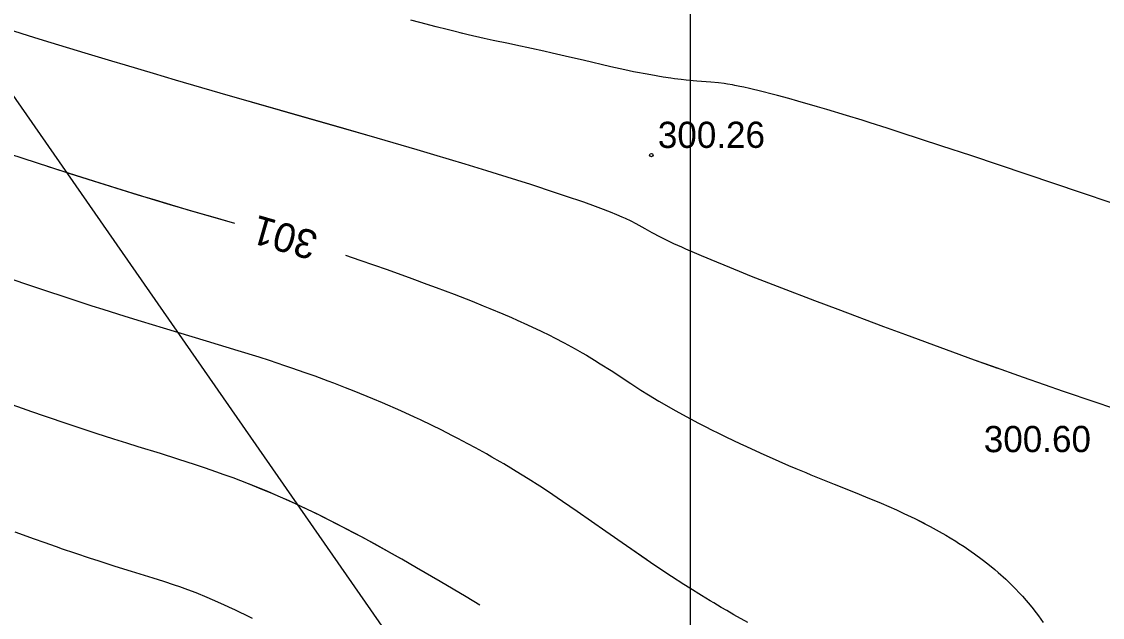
# Model space of a CAD drawing. Extents: x 7477803 to 7478145, y 5500698 to 5500984.
# Drawn here: x 7477982.63 to 7478010.69, y 5500826.14 to 5500841.6 of the extents above; entities that cross this region are included whole.
import ezdxf

# ---------------------------------------------------------------- set-up
doc = ezdxf.new("R2010")
doc.units = 0
for name, color, linetype in [('gr_klasy', 7, 'Continuous'), ('pkt_wys', 7, 'Continuous'), ('robocza49', 7, 'Continuous'), ('warst_ciagla', 7, 'Continuous'), ('warst_opis', 7, 'Continuous'), ('warst_pogrub', 7, 'Continuous'), ('warst_przeryw', 7, 'Continuous')]:
    doc.layers.add(name, color=color, linetype=linetype)

# ---------------------------------------------------------------- blocks, each defined once
blk = doc.blocks.new('801_1')
at = {"layer": 'pkt_wys'}
blk.add_circle((0, 0), 0.045, dxfattribs=at)
blk.add_circle((0, 0), 0.045, dxfattribs=at)

msp = doc.modelspace()

# ---------------------------------------------------------------- linework, layer by layer
at = {"layer": 'gr_klasy'}
msp.add_lwpolyline([(7477998.08, 5500817.16), (7477980.49, 5500842.45)], dxfattribs=at)
at = {"layer": 'robocza49'}
msp.add_line((7478000, 5500750), (7478000, 5500973.047), dxfattribs=at)
at = {"layer": 'warst_ciagla'}
for points in [[(7477982.322, 5500838.165), (7477983.358, 5500837.827), (7477983.907, 5500837.651), (7477984.763, 5500837.382), (7477985.648, 5500837.108), (7477986.098, 5500836.972), (7477987.01, 5500836.7), (7477987.468, 5500836.566), (7477988.155, 5500836.369)], [(7477983.299, 5500837.846), (7477984.198, 5500837.559), (7477984.664, 5500837.413), (7477985.38, 5500837.191), (7477986.111, 5500836.968), (7477986.48, 5500836.857), (7477987.223, 5500836.637), (7477987.596, 5500836.529), (7477988.155, 5500836.369)], [(7477991.039, 5500835.541), (7477991.416, 5500835.41), (7477992.12, 5500835.163), (7477992.758, 5500834.933), (7477993.15, 5500834.79), (7477993.396, 5500834.698), (7477993.857, 5500834.524), (7477994.325, 5500834.342), (7477994.611, 5500834.228), (7477994.79, 5500834.155), (7477995.123, 5500834.017), (7477995.353, 5500833.918), (7477995.496, 5500833.855), (7477995.764, 5500833.735), (7477996.122, 5500833.566), (7477996.336, 5500833.461), (7477996.469, 5500833.394), (7477996.716, 5500833.264), (7477997.003, 5500833.107), (7477997.18, 5500833.006), (7477997.292, 5500832.941), (7477997.504, 5500832.814), (7477997.653, 5500832.722), (7477997.934, 5500832.544), (7477998.451, 5500832.206), (7477998.706, 5500832.041), (7477998.904, 5500831.918), (7477999.175, 5500831.755), (7477999.315, 5500831.673), (7477999.601, 5500831.509), (7477999.999, 5500831.292), (7478000.205, 5500831.183), (7478000.362, 5500831.101), (7478000.576, 5500830.993), (7478000.685, 5500830.938), (7478000.933, 5500830.816), (7478001.273, 5500830.654), (7478001.446, 5500830.573), (7478001.801, 5500830.41), (7478002.29, 5500830.194), (7478002.542, 5500830.086), (7478002.733, 5500830.005), (7478002.992, 5500829.898), (7478003.123, 5500829.844), (7478003.726, 5500829.601), (7478004.269, 5500829.383), (7478004.541, 5500829.272), (7478004.946, 5500829.103), (7478005.343, 5500828.929), (7478005.537, 5500828.841), (7478005.823, 5500828.704), (7478006.078, 5500828.576)], [(7477991.039, 5500835.541), (7477991.416, 5500835.41), (7477992.12, 5500835.163), (7477992.758, 5500834.933), (7477993.15, 5500834.79), (7477993.396, 5500834.698), (7477993.857, 5500834.524), (7477994.325, 5500834.342), (7477994.611, 5500834.228), (7477994.79, 5500834.155), (7477995.123, 5500834.017), (7477995.353, 5500833.918), (7477995.496, 5500833.855), (7477995.764, 5500833.735), (7477996.122, 5500833.566), (7477996.336, 5500833.461), (7477996.469, 5500833.394), (7477996.716, 5500833.264), (7477997.003, 5500833.107), (7477997.18, 5500833.006), (7477997.292, 5500832.941), (7477997.504, 5500832.814), (7477997.653, 5500832.722), (7477997.934, 5500832.544), (7477998.451, 5500832.206), (7477998.706, 5500832.041), (7477998.904, 5500831.918), (7477999.175, 5500831.755), (7477999.315, 5500831.673), (7477999.601, 5500831.509), (7477999.999, 5500831.292), (7478000.205, 5500831.183), (7478000.362, 5500831.101), (7478000.576, 5500830.993), (7478000.685, 5500830.938), (7478000.933, 5500830.816), (7478001.273, 5500830.654), (7478001.446, 5500830.573), (7478001.801, 5500830.41), (7478002.29, 5500830.194), (7478002.542, 5500830.086), (7478002.733, 5500830.005), (7478002.992, 5500829.898), (7478003.123, 5500829.844), (7478003.726, 5500829.601), (7478004.269, 5500829.383), (7478004.541, 5500829.272), (7478004.946, 5500829.103), (7478005.343, 5500828.929), (7478005.537, 5500828.841), (7478005.823, 5500828.704), (7478006.099, 5500828.565), (7478006.219, 5500828.501), (7478006.377, 5500828.415), (7478006.454, 5500828.372), (7478006.625, 5500828.273), (7478006.737, 5500828.207), (7478006.883, 5500828.116), (7478006.955, 5500828.071), (7478007.097, 5500827.978), (7478007.281, 5500827.853), (7478007.371, 5500827.79), (7478007.567, 5500827.645), (7478007.71, 5500827.534), (7478007.895, 5500827.384), (7478007.984, 5500827.308), (7478008.178, 5500827.133), (7478008.262, 5500827.054), (7478008.371, 5500826.948), (7478008.424, 5500826.895), (7478008.54, 5500826.773), (7478008.616, 5500826.691), (7478008.713, 5500826.58), (7478008.761, 5500826.524), (7478008.854, 5500826.412), (7478008.973, 5500826.259), (7478009.03, 5500826.182), (7478009.154, 5500826.006)], [(7477994.526, 5500826.461), (7477994.17, 5500826.675), (7477993.501, 5500827.073), (7477992.883, 5500827.432), (7477992.499, 5500827.652), (7477992.254, 5500827.79), (7477991.791, 5500828.047), (7477991.308, 5500828.308), (7477991.008, 5500828.466), (7477990.817, 5500828.565), (7477990.454, 5500828.748), (7477990.198, 5500828.873), (7477990.034, 5500828.952), (7477989.723, 5500829.097), (7477989.575, 5500829.165), (7477989.29, 5500829.29), (7477989.021, 5500829.404), (7477988.849, 5500829.475), (7477988.519, 5500829.607), (7477988.121, 5500829.759), (7477987.866, 5500829.853), (7477987.701, 5500829.912), (7477987.378, 5500830.024), (7477987.143, 5500830.103), (7477986.686, 5500830.251), (7477986.242, 5500830.39), (7477985.655, 5500830.57), (7477985.36, 5500830.662), (7477985.024, 5500830.768), (7477984.567, 5500830.914), (7477984.335, 5500830.99), (7477983.864, 5500831.146), (7477983.223, 5500831.365), (7477982.895, 5500831.478), (7477982.144, 5500831.744)], [(7477992.472, 5500827.667), (7477991.863, 5500828.008), (7477991.487, 5500828.212), (7477991.25, 5500828.339), (7477990.803, 5500828.571), (7477990.492, 5500828.729), (7477990.294, 5500828.827), (7477989.921, 5500829.005), (7477989.745, 5500829.087), (7477989.41, 5500829.238), (7477989.097, 5500829.373), (7477988.898, 5500829.455), (7477988.519, 5500829.607), (7477988.121, 5500829.759), (7477987.866, 5500829.853), (7477987.701, 5500829.912), (7477987.378, 5500830.024), (7477987.143, 5500830.103), (7477986.686, 5500830.251), (7477986.242, 5500830.39), (7477985.655, 5500830.57), (7477985.36, 5500830.662), (7477985.024, 5500830.768), (7477984.567, 5500830.914), (7477984.335, 5500830.99), (7477983.864, 5500831.146), (7477983.223, 5500831.365), (7477982.895, 5500831.478), (7477982.144, 5500831.744)]]:
    msp.add_lwpolyline(points, dxfattribs=at)
at = {"layer": 'warst_pogrub'}
for points in [[(7478010.123, 5500837.166), (7478008.739, 5500837.631), (7478007.273, 5500838.121), (7478006.524, 5500838.369), (7478005.44, 5500838.723), (7478005.098, 5500838.833), (7478004.66, 5500838.972), (7478004.449, 5500839.038), (7478004.043, 5500839.164), (7478003.534, 5500839.318), (7478003.293, 5500839.39), (7478002.786, 5500839.536), (7478002.55, 5500839.602), (7478002.253, 5500839.682), (7478002.113, 5500839.719), (7478001.848, 5500839.786), (7478001.527, 5500839.863), (7478001.38, 5500839.895), (7478001.276, 5500839.917), (7478001.146, 5500839.942), (7478001.084, 5500839.953), (7478000.954, 5500839.975), (7478000.873, 5500839.988), (7478000.722, 5500840.008), (7478000.52, 5500840.028), (7478000.156, 5500840.055), (7477999.879, 5500840.081), (7477999.751, 5500840.095), (7477999.577, 5500840.117), (7477999.488, 5500840.129), (7477999.284, 5500840.16), (7477998.966, 5500840.213), (7477998.82, 5500840.24), (7477998.621, 5500840.278), (7477998.52, 5500840.298), (7477998.288, 5500840.347), (7477997.93, 5500840.427), (7477997.207, 5500840.597), (7477996.856, 5500840.679), (7477996.405, 5500840.781), (7477996.187, 5500840.83), (7477995.87, 5500840.899), (7477995.464, 5500840.986), (7477995.268, 5500841.026), (7477994.872, 5500841.108), (7477994.644, 5500841.157), (7477994.226, 5500841.254), (7477993.679, 5500841.39), (7477993.392, 5500841.464), (7477992.967, 5500841.575), (7477992.736, 5500841.636)], [(7478011.612, 5500836.666), (7478008.739, 5500837.631), (7478007.273, 5500838.121), (7478006.524, 5500838.369), (7478005.44, 5500838.723), (7478005.098, 5500838.833), (7478004.66, 5500838.972), (7478004.449, 5500839.038), (7478004.043, 5500839.164), (7478003.534, 5500839.318), (7478003.293, 5500839.39), (7478002.786, 5500839.536), (7478002.55, 5500839.602), (7478002.253, 5500839.682), (7478002.113, 5500839.719), (7478001.848, 5500839.786), (7478001.527, 5500839.863), (7478001.38, 5500839.895), (7478001.276, 5500839.917), (7478001.146, 5500839.942), (7478001.084, 5500839.953), (7478000.954, 5500839.975), (7478000.873, 5500839.988), (7478000.722, 5500840.008), (7478000.52, 5500840.028), (7478000.156, 5500840.055), (7477999.879, 5500840.081), (7477999.751, 5500840.095), (7477999.577, 5500840.117), (7477999.488, 5500840.129), (7477999.284, 5500840.16), (7477998.966, 5500840.213), (7477998.82, 5500840.24), (7477998.621, 5500840.278), (7477998.52, 5500840.298), (7477998.288, 5500840.347), (7477997.93, 5500840.427), (7477997.207, 5500840.597), (7477996.856, 5500840.679), (7477996.405, 5500840.781), (7477996.187, 5500840.83), (7477995.87, 5500840.899), (7477995.464, 5500840.986), (7477995.268, 5500841.026), (7477994.872, 5500841.108), (7477994.644, 5500841.157), (7477994.226, 5500841.254), (7477994.004, 5500841.309)]]:
    msp.add_lwpolyline(points, dxfattribs=at)
at = {"layer": 'warst_przeryw'}
for points in [[(7478007.973, 5500832.599), (7478007.364, 5500832.818), (7478006.641, 5500833.082), (7478005.585, 5500833.47), (7478005.018, 5500833.68), (7478003.825, 5500834.126), (7478003.226, 5500834.352), (7478002.364, 5500834.681), (7478001.583, 5500834.987), (7478001.264, 5500835.115), (7478000.866, 5500835.276), (7478000.678, 5500835.354), (7478000.285, 5500835.519), (7478000.103, 5500835.598), (7477999.875, 5500835.697), (7477999.768, 5500835.745), (7477999.566, 5500835.837), (7477999.325, 5500835.952), (7477999.216, 5500836.006), (7477998.999, 5500836.118), (7477998.816, 5500836.22), (7477998.585, 5500836.35), (7477998.457, 5500836.418), (7477998.309, 5500836.489), (7477998.225, 5500836.528), (7477998.084, 5500836.589), (7477997.921, 5500836.655), (7477997.671, 5500836.751), (7477997.532, 5500836.802), (7477997.224, 5500836.912), (7477996.755, 5500837.073), (7477996.495, 5500837.16), (7477995.847, 5500837.369), (7477995.49, 5500837.482), (7477994.982, 5500837.64), (7477994.713, 5500837.723), (7477994.147, 5500837.895), (7477993.333, 5500838.139), (7477992.901, 5500838.267), (7477991.865, 5500838.57), (7477990.168, 5500839.06), (7477987.79, 5500839.743), (7477986.624, 5500840.082), (7477986.06, 5500840.247), (7477985.33, 5500840.464), (7477984.975, 5500840.57), (7477984.284, 5500840.778), (7477983.402, 5500841.048), (7477982.978, 5500841.179), (7477982.067, 5500841.466)], [(7478011.415, 5500831.417), (7478010.501, 5500831.723), (7478009.674, 5500832.002), (7478009.184, 5500832.171), (7478008.636, 5500832.363), (7478007.814, 5500832.656), (7478007.364, 5500832.818), (7478006.641, 5500833.082), (7478005.585, 5500833.47), (7478005.018, 5500833.68), (7478003.825, 5500834.126), (7478003.226, 5500834.352), (7478002.364, 5500834.681), (7478001.583, 5500834.987), (7478001.264, 5500835.115), (7478000.866, 5500835.276), (7478000.678, 5500835.354), (7478000.285, 5500835.519), (7478000.103, 5500835.598), (7477999.875, 5500835.697), (7477999.768, 5500835.745), (7477999.566, 5500835.837), (7477999.325, 5500835.952), (7477999.216, 5500836.006), (7477998.999, 5500836.118), (7477998.816, 5500836.22), (7477998.585, 5500836.35), (7477998.457, 5500836.418), (7477998.309, 5500836.489), (7477998.225, 5500836.528), (7477998.084, 5500836.589), (7477997.921, 5500836.655), (7477997.671, 5500836.751), (7477997.532, 5500836.802), (7477997.224, 5500836.912), (7477996.755, 5500837.073), (7477996.495, 5500837.16), (7477995.847, 5500837.369), (7477995.49, 5500837.482), (7477994.982, 5500837.64), (7477994.713, 5500837.723), (7477994.147, 5500837.895), (7477993.333, 5500838.139), (7477992.901, 5500838.267), (7477991.865, 5500838.57), (7477990.791, 5500838.881), (7477988.517, 5500839.534)], [(7477998.86, 5500827.632), (7477998.331, 5500827.996), (7477997.798, 5500828.37), (7477997.058, 5500828.89), (7477996.675, 5500829.153), (7477996.284, 5500829.416), (7477996.085, 5500829.547), (7477995.782, 5500829.74), (7477995.474, 5500829.931), (7477995.336, 5500830.015), (7477995.15, 5500830.125), (7477995.056, 5500830.18), (7477994.843, 5500830.302), (7477994.7, 5500830.383), (7477994.508, 5500830.49), (7477994.411, 5500830.543), (7477994.217, 5500830.648), (7477993.954, 5500830.786), (7477993.822, 5500830.854), (7477993.521, 5500831.006), (7477993.293, 5500831.118), (7477992.985, 5500831.265), (7477992.829, 5500831.338), (7477992.476, 5500831.499), (7477991.997, 5500831.709), (7477991.754, 5500831.812), (7477991.262, 5500832.013), (7477991.04, 5500832.1), (7477990.741, 5500832.215), (7477990.591, 5500832.272), (7477990.25, 5500832.397), (7477989.991, 5500832.49), (7477989.643, 5500832.611), (7477989.467, 5500832.671), (7477989.068, 5500832.803), (7477988.8, 5500832.889), (7477988.257, 5500833.059), (7477987.431, 5500833.31), (7477986.312, 5500833.645), (7477985.747, 5500833.816), (7477985.322, 5500833.947), (7477984.753, 5500834.126), (7477984.467, 5500834.217), (7477983.895, 5500834.402), (7477983.129, 5500834.655), (7477982.744, 5500834.785), (7477981.875, 5500835.084)], [(7478001.487, 5500826.012), (7478001.124, 5500826.212), (7478000.938, 5500826.319), (7478000.796, 5500826.402), (7478000.603, 5500826.516), (7478000.505, 5500826.575), (7478000.282, 5500826.711), (7477999.977, 5500826.901), (7477999.821, 5500826.999), (7477999.505, 5500827.204), (7477999.069, 5500827.491), (7477998.846, 5500827.642), (7477998.331, 5500827.996), (7477997.798, 5500828.37), (7477997.058, 5500828.89), (7477996.675, 5500829.153), (7477996.284, 5500829.416), (7477996.085, 5500829.547), (7477995.782, 5500829.74), (7477995.474, 5500829.931), (7477995.336, 5500830.015), (7477995.15, 5500830.125), (7477995.056, 5500830.18), (7477994.843, 5500830.302), (7477994.7, 5500830.383), (7477994.508, 5500830.49), (7477994.411, 5500830.543), (7477994.217, 5500830.648), (7477993.954, 5500830.786), (7477993.822, 5500830.854), (7477993.521, 5500831.006), (7477993.293, 5500831.118), (7477992.985, 5500831.265), (7477992.829, 5500831.338), (7477992.476, 5500831.499), (7477991.997, 5500831.709), (7477991.754, 5500831.812), (7477991.262, 5500832.013), (7477991.04, 5500832.1), (7477990.741, 5500832.215), (7477990.591, 5500832.272), (7477990.25, 5500832.397), (7477989.991, 5500832.49), (7477989.643, 5500832.611), (7477989.467, 5500832.671), (7477989.068, 5500832.803), (7477988.8, 5500832.889), (7477988.257, 5500833.059), (7477987.431, 5500833.31), (7477986.312, 5500833.645), (7477985.747, 5500833.816), (7477985.322, 5500833.947), (7477984.753, 5500834.126), (7477984.467, 5500834.217), (7477983.895, 5500834.402), (7477983.129, 5500834.655), (7477982.744, 5500834.785), (7477981.875, 5500835.084)], [(7477982.458, 5500828.361), (7477982.96, 5500828.179), (7477983.206, 5500828.092), (7477983.529, 5500827.979), (7477983.688, 5500827.924), (7477984.002, 5500827.817), (7477984.41, 5500827.681), (7477984.611, 5500827.616), (7477985.052, 5500827.475), (7477985.48, 5500827.344), (7477986.039, 5500827.172), (7477986.315, 5500827.083), (7477986.592, 5500826.99), (7477986.732, 5500826.941), (7477986.941, 5500826.865), (7477987.153, 5500826.784), (7477987.438, 5500826.668), (7477987.582, 5500826.607), (7477987.873, 5500826.479), (7477988.003, 5500826.419), (7477988.178, 5500826.337), (7477988.266, 5500826.294), (7477988.464, 5500826.196), (7477988.614, 5500826.12)]]:
    msp.add_lwpolyline(points, dxfattribs=at)

# ---------------------------------------------------------------- block references
at = {"layer": 'pkt_wys', "rotation": 0.0626175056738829}
msp.add_blockref('801_1', (7477998.98, 5500838.135), dxfattribs=at)

# ---------------------------------------------------------------- texts
at = {"layer": 'pkt_wys'}
for s, p in [('300.26', (7477999.149, 5500838.319)), ('300.60', (7478007.61, 5500830.428))]:
    msp.add_text(s, height=0.68, rotation=0.0626, dxfattribs=at).set_placement(p)
at = {"layer": 'warst_opis'}
msp.add_text('301', height=0.75, rotation=163.973, dxfattribs=at).set_placement((7477990.37, 5500836.123))

doc.saveas('drawing.dxf')
